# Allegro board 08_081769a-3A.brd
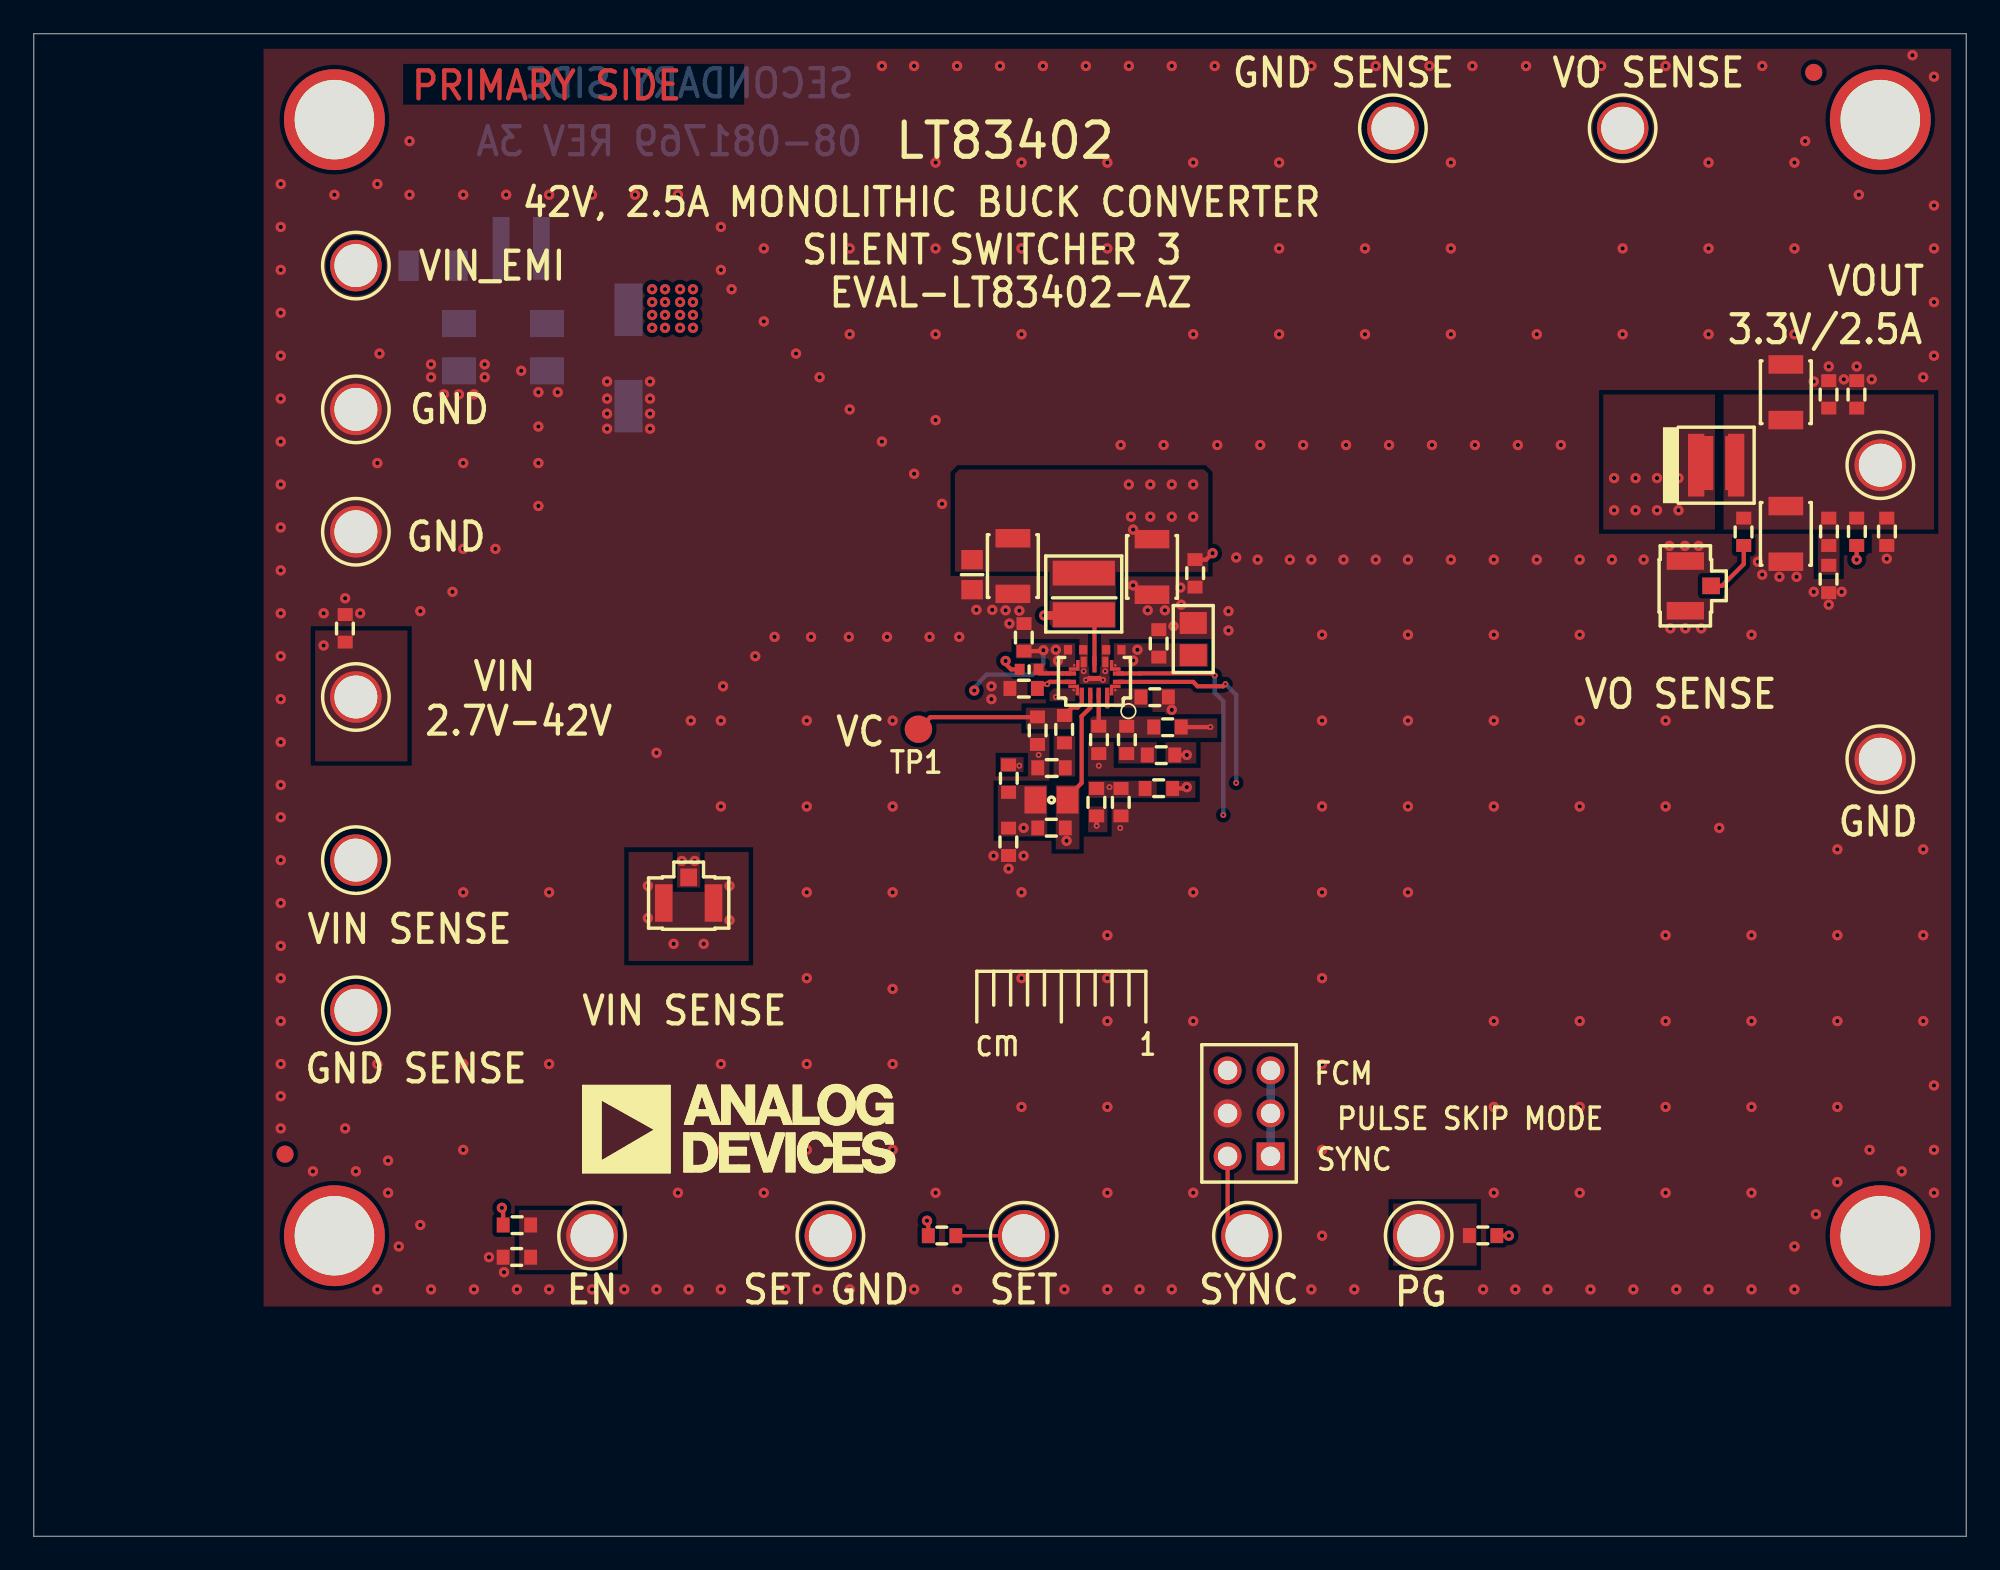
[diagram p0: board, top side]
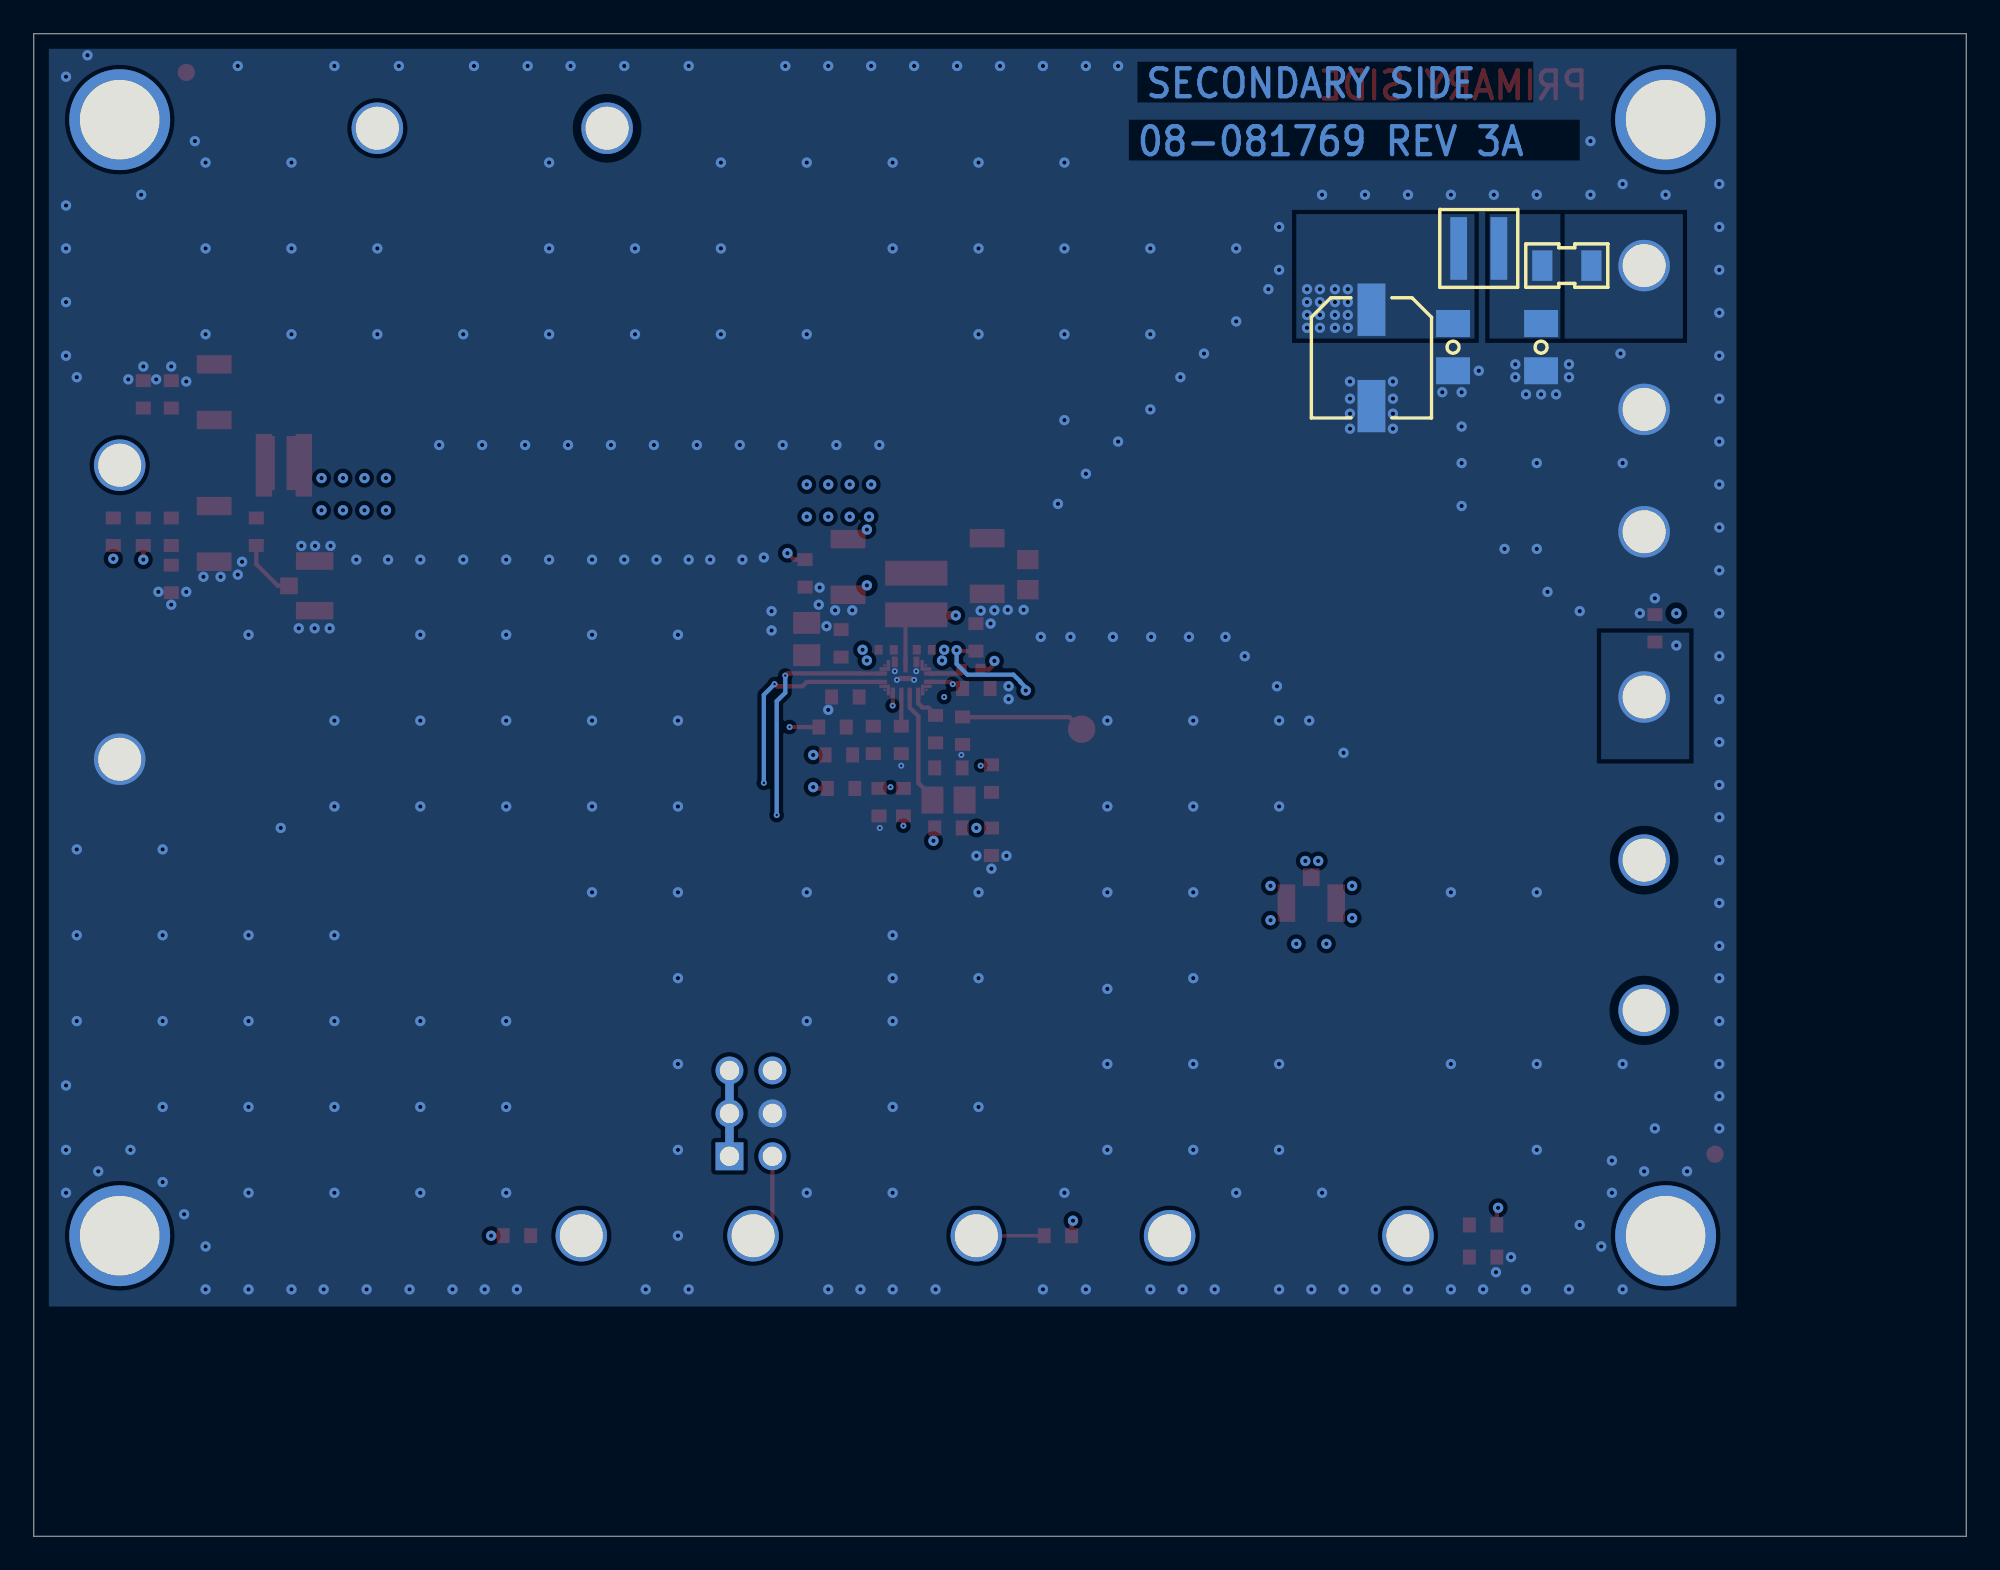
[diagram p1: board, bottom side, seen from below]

Outline 114.3 x 88.9 mm; copper layers: TOP, LAYER_2, LAYER_3, BOTTOM. Coordinates in mm from the lower left corner of the outline.
Outline path: 0,88.9 0,0 114.3,0 114.3,88.9 0,88.9

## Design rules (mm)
constraint set DEFAULT: min track width 0.203

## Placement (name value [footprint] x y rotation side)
C1  1uF  [C1206H71]  30.35 70.36 270 bottom
C2  2.2uF  [C0603]  18.41 53.72 90 top
C4  22uF  [CPLSMSQ260H315]  35.18 69.72 270 bottom
C5  4.7uF  [C0805H53]  68.58 53.09 90 top
C6  4.7uF  [C1206H71]  25.15 70.36 270 bottom
C7  1UF  [C0402#2]  63.88 52.45 180 top
C8  4700pF  [C0603]  60.2 45.47 180 top
C9  1UF  [C0402#2]  61.62 52.45 0 top
C10  2.2uF  [C0603]  68.68 56.97 270 top
C11  82PF  [C0603]  59.37 47.66 270 top
C12  1uF  [C0603]  58.55 50.17 180 top
C13  0.1uF  [C0402]  58.87 51.29 0 top
C14  1uF  [C0805H60]  60.2 43.56 180 top
C15  22uF  [C1210H106]  57.91 57.4 270 top
C16  22uF  [C1210H106]  66.14 57.35 270 top
C18  TBD0805  [C0805]  55.5 56.9 270 top
C19  22uF  [C1210H106]  103.63 67.69 90 top
C20  22uF  [C1210H106]  103.63 59.31 270 top
C21  2.2uF  [C0603]  109.6 59.44 270 top
C22  TBD0603  [C0603]  106.17 67.56 90 top
C23  TBD0603  [C0603]  107.82 67.56 90 top
C24  TBD0603  [C0603]  106.17 59.44 270 top
C25  1uF  [C0603]  58.57 53.19 90 top
C26  1uF  [C0603]  66.55 52.83 90 top
E1  2501-2-00-80-00-00-07-0  [CNMILLMAX2501]  19.05 75.18 90 top
E2  2501-2-00-80-00-00-07-0  [CNMILLMAX2501]  19.05 66.67 90 top
E3  2501-2-00-80-00-00-07-0  [CNMILLMAX2501]  19.05 40 90 top
E4  2501-2-00-80-00-00-07-0  [CNMILLMAX2501]  19.05 31.11 90 top
E5  2501-2-00-80-00-00-07-0  [CNMILLMAX2501]  71.75 17.78 0 top
E6  2501-2-00-80-00-00-07-0  [CNMILLMAX2501]  19.05 49.66 0 top
E7  2501-2-00-80-00-00-07-0  [CNMILLMAX2501]  19.05 59.44 0 top
E8  2501-2-00-80-00-00-07-0  [CNMILLMAX2501]  33.02 17.78 0 top
E9  2501-2-00-80-00-00-07-0  [CNMILLMAX2501]  81.92 17.78 0 top
E10  2501-2-00-80-00-00-07-0  [CNMILLMAX2501]  93.98 83.31 90 top
E11  2501-2-00-80-00-00-07-0  [CNMILLMAX2501]  80.39 83.31 270 top
E12  2501-2-00-80-00-00-07-0  [CNMILLMAX2501]  109.22 63.37 0 top
E13  2501-2-00-80-00-00-07-0  [CNMILLMAX2501]  109.22 45.97 0 top
E14  2501-2-00-80-00-00-07-0  [CNMILLMAX2501]  58.55 17.78 0 top
E15  2501-2-00-80-00-00-07-0  [CNMILLMAX2501]  47.12 17.78 0 top
FB1  800OHM AT 100MHZ  [L1206H71]  23.62 75.18 0 bottom
J5  RSP-122811-01  [CNSMASQ102H56]  38.73 37.47 180 top
J6  RSP-122811-01  [CNSMASQ102H56]  97.69 56.24 90 top
JP1  TSW-103-07-F-D  [CNSAMTEC2X3H330LD36]  73.15 22.48 90 top
L1  2.2UH  [LSMSQ157H83]  62.1 55.75 90 top
L2  4.7UH  [LSMSQ161H83]  28.83 76.2 0 bottom
L3  2.2UH  [LSMSQ157H122]  99.51 63.37 0 top
NOREF  -  []  343.12 241.69 0 top
NOREF#2  -  []  113.67 13.33 90 top
NOREF#3  -  []  113.67 88.27 180 top
NOREF#4  -  []  12.7 88.9 0 top
NOREF#5  -  [unnamed#2]  17.78 83.82 0 top
NOREF#6  -  [unnamed#2]  17.78 17.78 0 top
NOREF#7  -  []  12.7 12.7 90 top
NOREF#8  -  []  -102.74 -190.75 0 top
NOREF#9  -  []  275.21 77.85 0 top
NOREF#10  -  [unnamed#2]  109.22 17.78 0 top
NOREF#11  -  []  178.18 232.41 0 top
NOREF#12  -  [unnamed#2]  109.22 83.82 0 top
NOREF#13  -  []  61.77 101.24 0 top
NOREF#14  -  []  58.93 34.67 0 top
NOREF#15  -  [unnamed#2]  14.86 22.61 0 top
NOREF#16  -  [unnamed#2]  105.28 86.61 0 top
NOREF#17  -  []  13.33 13.33 0 top
NOREF#18  -  []  -60.71 -173.48 0 top
NOREF#19  -  []  13.33 88.27 270 top
NOREF#20  -  []  350.14 178.18 0 top
R1  1K  [R0603]  60.96 47.75 270 top
R2  TBD0603  [R0603]  53.72 17.78 180 top
R3  100K  [R0603]  28.57 18.41 0 top
R4  47.5K  [R0603]  66.29 49.66 0 top
R5  TBD0603  [R0603]  28.57 16.51 180 top
R6  33.2K  [R0603]  60.2 41.91 180 top
R7  0  [R0603]  64.64 47.12 90 top
R8  0.001  [R0612]  99.7 63.5 0 top
R9  TBD0603  [R0603]  67.06 47.88 0 top
R10  280K  [R0603]  66.55 44.25 180 top
R11  49.9K  [R0603]  64.31 43.43 270 top
R12  100K  [R0603]  85.73 17.79 180 top
R13  TBD0603  [R0603]  106.17 56.64 270 top
R14  0  [R0603]  66.67 46.23 0 top
R15  TBD0603  [R0603]  62.99 47.12 90 top
R16  TBD0603  [R0603]  107.82 59.44 90 top
R17  TBD0603  [R0603]  57.66 44.83 90 top
R18  0  [R0603]  57.66 41.09 270 top
R19  TBD0603  [R0603]  62.86 43.43 270 top
R22  0  [R0603]  101.14 59.44 270 top
TP1  NCTARGET_PAD_C62AU  [TPSMC62]  52.32 47.75 0 top
U1  LT83402  [QFN15_CP-15-1]  62.74 50.8 180 top

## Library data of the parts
C1 = CAP: Tolerance: 10; User Part Number: UPN; alternate symbols: (C1206H71); part number: CAP_SM-1UF,50V,10,E030213,C1206H71; tolerance: 10
C2 = CAP: Tolerance: 10; User Part Number: UPN; alternate symbols: (C0603); part number: CAP_SM-2.2UF,50V,10,E024995,C0603; tolerance: 10
C4 = CAPP: Tolerance: 20; User Part Number: UPN; alternate symbols: (CPLSMSQ260H315); part number: CAPP_SM-22UF,63V,20,E033596,CPLSMSQ260H315; tolerance: 20
C5 = CAP: Tolerance: 10; User Part Number: UPN; alternate symbols: (C0805H53); part number: CAP_SM-4.7UF,50V,10,E028468,C0805H53; tolerance: 10
C6 = CAP: Tolerance: 10; User Part Number: UPN; alternate symbols: (C1206H71); part number: CAP_SM-4.7UF,50V,10,E026699,C1206H71; tolerance: 10
C7 C9 = CAP: User Part Number: UPN; Tolerance: 10; alternate symbols: (C0402L); part number: CAP_SM-1UF,50V,10,E064438,C0402; tolerance: 10
C8 = CAP: Tolerance: 10; User Part Number: UPN; alternate symbols: (C0603); part number: CAP_SM-4700PF,50V,10,E000427,C0603; tolerance: 10
C10 C21 = CAP: Tolerance: 10; User Part Number: UPN; alternate symbols: (C0603); part number: CAP_SM-2.2UF,25V,10,E031885,C0603; tolerance: 10
C11 = CAP: Tolerance: 5; User Part Number: UPN; alternate symbols: (C0603); part number: CAP_SM-82PF,50V,5,E042666,C0603; tolerance: 5
C12 = CAP: Tolerance: 10; User Part Number: UPN; alternate symbols: (C0603); part number: CAP_SM-1UF,25V,10,E033832,C0603; tolerance: 10
C13 = CAP: Tolerance: 10; User Part Number: UPN; alternate symbols: (C0402); part number: CAP_SM-0.1UF,50V,10,E028943,C0402; tolerance: 10
C14 = CAP: Tolerance: 10; User Part Number: UPN; alternate symbols: (C0805H60); part number: CAP_SM-1UF,50V,10,E030886,C0805H60; tolerance: 10
C15 C16 C19 C20 = CAP: Tolerance: 10; User Part Number: UPN; alternate symbols: (C1210H106); part number: CAP_SM-22UF,25V,10,E025745,C1210H106; tolerance: 10
C18 = CAP: User Part Number: UPN; alternate symbols: (C0805); part number: CAP_SM-TBD0805,TBD0805,TBD0805,E000383,C0805
C22-C24 = CAP: User Part Number: UPN; alternate symbols: (C0603); part number: CAP_SM-TBD0603,TBD0603,TBD0603,E000382,C0603
C25 C26 = CAP: Tolerance: 10; User Part Number: UPN; alternate symbols: (C0603); part number: CAP_SM-1UF,50V,10,E023087,C0603; tolerance: 10
E1-E15 = CNTP1P: User Part Number: UPN; Tolerance: N/A; alternate symbols: (CNMILLMAX2501); part number: CNTP1P_TH-2501-2-00-80-00-00-07-0,E031108,CNMILLMAX2501; tolerance: N/A
FB1 = FERRITE: User Part Number: UPN; Tolerance: 25; alternate symbols: (L1206H71); part number: FERRITE_SM-800OHM AT 100MHZ,25,E067875,L1206H71; tolerance: 25
J5 J6 = CNBNC3P: User Part Number: UPN; Tolerance: N/A; alternate symbols: (CNSMASQ102H56); part number: CNBNC3P_SM-RSP-122811-01,E033920,CNSMASQ102H56; tolerance: N/A
JP1 = CN6P_ODD_EVEN: Tolerance: N/A; User Part Number: UPN; alternate symbols: (CNSAMTEC2X3H330LD36); part number: CN6P_ODD_EVEN_TH-TSW-103-07-F-D,E031502,CNSAMTEC2X3H330LD36; tolerance: N/A
L1 = IND: User Part Number: UPN; Tolerance: 20; alternate symbols: (LSMSQ157H83); part number: IND_SM-2.2UH,20,E051506,LSMSQ157H83; tolerance: 20
L2 = IND: User Part Number: UPN; Tolerance: 20; alternate symbols: (LSMSQ161H83); part number: IND_SM-4.7UH,20,E046383,LSMSQ161H83; tolerance: 20
L3 = IND: User Part Number: UPN; Tolerance: 20; alternate symbols: (LSMSQ157H122); part number: IND_SM-2.2UH,20,E054929,LSMSQ157H122; tolerance: 20
R1 = RES: Tolerance: 1; User Part Number: UPN; alternate symbols: (R0603); part number: RES_SM-1K,E003678,1/10W,1,R0603; tolerance: 1
R2 R5 R9 R13 R15-R17 R19 = RES: User Part Number: UPN; alternate symbols: (R0603); part number: RES_SM-TBD0603,E004050,TBD0603,TBD0603,R0603
R3 R12 = RES: Tolerance: 1; User Part Number: UPN; alternate symbols: (R0603); part number: RES_SM-100K,E010279,1/10W,1,R0603; tolerance: 1
R4 = RES: Tolerance: 1; User Part Number: UPN; alternate symbols: (R0603); part number: RES_SM-47.5K,E032237,1/10W,1,R0603; tolerance: 1
R6 = RES: Tolerance: 1; User Part Number: UPN; alternate symbols: (R0603); part number: RES_SM-33.2K,E028266,1/10W,1,R0603; tolerance: 1
R7 R14 R18 R22 = RES: Tolerance: JUMPER; User Part Number: UPN; alternate symbols: (R0603); part number: RES_SM-0,E007502,1/10W,JUMPER,R0603; tolerance: JUMPER
R8 = RES: User Part Number: UPN; Tolerance: 1; alternate symbols: (R0612); part number: RES_SM-0.001,E065605,1W,1,R0612; tolerance: 1
R10 = RES: Tolerance: 1; User Part Number: UPN; alternate symbols: (R0603); part number: RES_SM-280K,E020071,1/10W,1,R0603; tolerance: 1
R11 = RES: Tolerance: 1; User Part Number: UPN; alternate symbols: (R0603); part number: RES_SM-49.9K,E015342,1/10W,1,R0603; tolerance: 1
TP1 = NC1P: Tolerance: N/A; User Part Number: UPN; alternate symbols: (TPSMC62); part number: NC1P_SM-NCTARGET_PAD_C62AU,E050423,TPSMC62; tolerance: N/A
U1 = ADLT83402: User Part Number: UPN; Tolerance: N/A; alternate symbols: (QFN15_CP-15-1); part number: ADLT83402_SM-LT83402,E065562,QFN15_CP-15-1; tolerance: N/A

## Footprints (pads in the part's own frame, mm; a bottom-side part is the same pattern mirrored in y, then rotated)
C0402
  rect 0.584x0.66 smd: 1(-0.559,0) 2(0.559,0)
C0402#2
  rect 0.483x0.559 smd: 1(-0.45,0) 2(0.45,0)
C0603
  rect 0.762x0.889 smd: 1(-0.813,0) 2(0.813,0)
C0805
  rect 1.143x1.27 smd: 1(-0.889,0) 2(0.889,0)
C0805H53
  rect 1.295x1.6 smd: 1(-0.953,0) 2(0.953,0)
C0805H60
  rect 1.295x1.6 smd: 1(-0.953,0) 2(0.953,0)
C1206H71
  rect 1.6x2.007 smd: 1(-1.397,0) 2(1.397,0)
C1210H106
  rect 1.092x2.057 smd: 1(-1.646,0) 2(1.646,0)
CNMILLMAX2501
  round 3.048 hole 2.54: 1(0,0)
CNSAMTEC2X3H330LD36
  rect 1.651x1.651 hole 1.143: 1(0,0)
  round 1.651 hole 1.143: 2(0,2.54) 3(2.54,0) 4(2.54,2.54) 5(5.08,0) 6(5.08,2.54)
CNSMASQ102H56
  rect 0.991x1.041 smd: 1(0,-1.521)
  rect 1.041x2.21 smd: 2(-1.471,0) 3(1.471,0)
CPLSMSQ260H315
  rect 3.099x1.651 smd: N(2.85,0) P(-2.85,0)
L1206H71
  rect 1.194x1.803 smd: 1(-1.45,0) 2(1.45,0)
LSMSQ157H83
  rect 1.473x3.683 smd: 1(-1.232,0) 2(1.232,0)
LSMSQ157H122
  rect 0.965x3.708 smd: 1(-1.181,0) 2(1.181,0)
LSMSQ161H83
  rect 0.991x3.708 smd: 1(-1.19,0) 2(1.19,0)
QFN15_CP-15-1
  custom 0.159x0.159 smd: 1(-1.229,0.729) 4(-1.229,-0.729) 8(1.2,-0.729) 11(1.229,0.729)
  rect 0.66x0.254 smd: 2(-1.42,0.25) 3(-1.42,-0.25) 9(1.42,-0.25) 10(1.42,0.25)
  rect 0.356x0.635 smd: 5(-0.64,-0.932) 7(0.64,-0.932)
  rect 0.254x0.94 smd: 6(0,-0.78)
  rect 0.254x0.66 smd: 12(0.75,0.92) 13(0.25,0.92) 14(-0.25,0.92) 15(-0.75,0.92)
  rect 0.813x0.305 smd: 16(0,0.051)
R0603
  rect 0.762x0.889 smd: 1(-0.813,0) 2(0.813,0)
R0612
  rect 0.94x3.2 smd: 1(-0.82,0) 2(0.82,0)
TPSMC62
  round 1.626 smd: 1(0,0)
unnamed#2
  round 5.969 hole 4.699 unplated: (0,0)

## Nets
GND_POWER: C1.2(N2) C2.2(N2) C4.N(N2) C5.2(N2) C6.2(N2) C7.2(N2) C8.2(N2) C9.2(N2) C10.2(N2) C11.2(N2) C12.2(N2) C15.2(N2) C16.2(N2) C18.2(N2) C19.2(N2) C20.2(N2) C21.2(N2) C22.2(N2) C23.2(N2) C25.2(N2) C26.2(N2) E2.1(N1) E4.1(N1) E7.1(N1) E11.1(N1) E13.1(N1) J5.2 J5.3(SH2) J6.2 J6.3(SH2) JP1.4 R4.2(N2) R5.2(N2) R11.2(N2) R13.2(N2) R15.1 R17.2(N2) R18.2(N2) U1.5 U1.7 U1.16
VIN: C1.1 C2.1 C4.P C5.1 C7.1 C9.1 C25.1 C26.1 E3.1(N1) E6.1(N1) J5.1 L2.2(N2) R3.1 U1.4 U1.8(VIN_2)
BST: C13.2(N2) U1.9
INTVCC: C12.1 JP1.6(N6) R19.2(N2) U1.10
OUTS: R7.2(N2) R9.1 R15.2(N2) U1.14
PG: E9.1(N1) R12.2(N2) U1.2
PGFB: R10.2(N2) R11.1 R19.1 U1.15
SET: C14.1 R2.2(N2) R6.1 U1.13
SW: C13.1 L1.1 U1.6
SYNC: JP1.1 JP1.3 JP1.5 U1.3
UNNAMED_2_ADLT83402_I194_EN: E8.1(N1) R3.2(N2) R5.1 U1.11
UNNAMED_2_ADLT83402_I194_RT: R4.1 U1.1
UNNAMED_2_CAP_I105_N2: C24.2(N2) R13.1
UNNAMED_2_CAP_I141_N1: C10.1 C15.1 C16.1 C18.1 E10.1(N1) L1.2(N2) L3.1 R8.1 R10.1 R14.2(N2)
UNNAMED_2_CAP_I218_N1: C6.1 FB1.2(N2) L2.1
UNNAMED_2_CAP_I232_N2: C14.2(N2) E15.1(N1) R6.2(N2) R17.1 R18.1
UNNAMED_2_CAP_I244_N1: C8.1 R1.2(N2)
UNNAMED_2_CN6PODDEVEN_I122_N2: E5.1(N1) JP1.2
UNNAMED_2_CNBNC3P_I240_CNTR: J6.1 R22.2(N2)
UNNAMED_2_CNTP1P_I204_N1: E1.1(N1) FB1.1
UNNAMED_2_CNTP1P_I231_N1: E14.1(N1) R2.1
UNNAMED_2_RES_I157_N1: R7.1 R14.1
UNNAMED_2_RES_I219_N2: R9.2(N2) R16.1
VC: C11.1 R1.1 TP1.1(N1) U1.12
VOUT: C19.1 C20.1 C21.1 C22.1 C23.1 C24.1 E12.1(N1) L3.2(N2) R8.2(N2) R12.1 R16.2(N2) R22.1

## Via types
v1: diameter 0.61, hole 0.254, TOP to BOTTOM, 389 vias
v2: diameter 0.356, hole 0.152, TOP to BOTTOM, 18 vias

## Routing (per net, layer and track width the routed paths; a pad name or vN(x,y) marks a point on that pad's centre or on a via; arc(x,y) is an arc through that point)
GND_POWER: length 205.3
  TOP w0.254: 22.8,54.67 v1(22.86,54.74)
  LAYER_3 w0.254: v1(109.6,57.84) 109.09,57.33 109.09,55.12 100.2,46.23 70.36,46.23 69.72,45.59 69.72,44.07 68.83,43.18 62.48,43.18 60.07,45.59 v2(58.29,45.59) ; E4.1 47.12,31.11 52.83,36.83 52.83,48.51 55.12,50.8 56.39,50.8 56.64,50.55 v1(56.64,50.29) ; v1(65.02,56.26) 65.02,57.91 62.36,60.58 62.36,69.22 67.12,73.98 75.37,73.98 75.44,73.91 85.6,73.91 87.76,76.07 87.76,82.42 86.87,83.31 E11.1 ; 37.47,40.26 37.47,42.16 36.07,43.56 17.02,43.56 15.49,45.08 15.49,52.96 v1(17.14,54.61)
  vias: v1(14.6,80.01) v1(14.6,77.47) v1(14.6,74.93) v1(14.6,72.39) v1(14.6,69.85) v1(14.6,67.31) v1(14.6,64.77) v1(14.6,62.23) v1(14.6,59.69) v1(14.6,57.15) v1(14.6,54.61) v1(14.6,52.07) v1(14.6,49.53) v1(14.6,46.99) v1(14.6,44.45) v1(14.6,42.55) v1(14.6,40) v1(14.6,37.47) v1(14.6,34.92) v1(14.6,33.02) v1(14.6,30.48) v1(14.6,27.94) v1(14.6,26.04) v1(14.6,24.13) v1(16.51,21.59) v1(17.78,79.38) v1(18.41,55.5) v1(18.41,24.13) v1(19.05,21.59) v1(19.3,54.61) v1(20.32,80.01) v1(20.32,63.5) v1(20.32,27.94) v1(20.32,14.6) v1(20.45,69.98) v1(20.95,22.23) v1(20.95,20.32) v1(21.59,17.14) v1(22.23,82.55) v1(22.23,79.38) v1(22.86,18.41) v1(23.49,69.34) v1(23.49,68.58) v1(23.49,14.6) v1(24.26,67.56) v1(24.77,55.88) v1(25.15,67.56) v1(25.4,79.38) v1(25.4,63.5) v1(25.4,58.42) v1(25.4,38.1) v1(25.4,27.94) v1(25.4,22.86) v1(26.04,67.56) v1(26.04,14.6) v1(26.67,69.34) v1(26.67,68.58) v1(26.92,16.51) v1(27.3,58.42) v1(27.81,15.62) v1(27.94,79.38) v1(28.57,14.6) v1(28.83,68.96) v1(29.84,67.69) v1(29.84,65.66) v1(29.84,63.5) v1(29.84,60.96) v1(30.48,79.38) v1(30.48,38.1) v1(30.48,27.94) v1(30.48,14.6) v1(30.99,67.69) v1(33.02,79.38) v1(33.02,14.6) v1(33.91,68.33) v1(33.91,67.31) v1(33.91,66.42) v1(33.91,65.53) v1(34.92,14.6) v1(35.56,79.38) v1(36.32,38.48) v1(36.32,36.58) v1(36.45,68.33) v1(36.45,67.31) v1(36.45,66.42) v1(36.45,65.53) v1(36.83,46.36) v1(36.83,14.6) v1(37.85,35.05) v1(38.1,79.38) v1(38.1,20.32) v1(38.73,14.6) v1(38.86,48.26) v1(39.62,35.05) v1(40.64,77.47) v1(40.64,74.93) v1(40.64,48.26) v1(40.64,43.18) v1(40.64,27.94) v1(40.64,22.86) v1(40.64,14.6) v1(40.77,50.29) v1(41.15,38.48) v1(41.15,36.45) v1(41.27,73.79) v1(42.67,52.07) v1(43.18,76.2) v1(43.18,71.88) v1(43.18,20.32) v1(43.81,53.21) v1(44.45,14.6) v1(45.08,69.98) v1(45.72,48.26) v1(45.72,43.18) v1(45.72,38.1) v1(45.72,33.02) v1(45.72,27.94) v1(45.72,22.86) v1(45.97,53.21) v1(46.36,14.6) v1(46.48,68.58) v1(48.21,53.21) v1(48.26,76.2) v1(48.26,71.12) v1(48.26,66.67) v1(48.26,14.6) v1(50.17,87) v1(50.17,64.77) v1(50.47,53.21) v1(50.8,48.26) v1(50.8,43.18) v1(50.8,38.1) v1(50.8,32.38) v1(50.8,27.94) v1(50.8,22.86) v1(52.07,87) v1(52.07,62.86) v1(52.07,14.6) v1(52.98,53.21) v1(53.34,81.28) v1(53.34,76.2) v1(53.34,71.12) v1(53.34,66.04) v1(53.34,20.32) v1(53.72,61.09) v1(54.61,87) v1(54.61,14.6) v1(54.74,53.21) v1(55.75,54.81) v1(56.64,49.53) v1(56.69,54.81) v1(56.77,40.26) v1(57.15,87) v1(57.48,54.79) v1(57.71,54) v1(57.66,39.5) v1(58.29,54.76) v1(58.42,81.28) v1(58.42,76.2) v1(58.42,71.12) v1(58.42,38.1) v1(58.42,33.02) v1(58.42,25.4) v1(58.55,40.26) v1(59.69,87) v1(60.96,14.6) v1(62.23,87) v1(63.5,81.28) v1(63.5,76.2) v1(63.5,35.56) v1(63.5,33.02) v1(63.5,30.48) v1(63.5,25.4) v1(63.5,20.32) v1(63.5,14.6) v1(64.29,64.57) v1(64.77,87) v1(65.41,14.6) v1(65.89,54.79) v1(66.83,64.57) v1(66.9,54.79) v1(67.31,87) v1(67.31,48.89) v1(67.31,14.6) v1(67.41,53.85) v1(67.82,56.13) v1(67.87,55.12) v1(68.58,81.28) v1(68.58,71.12) v1(68.58,38.1) v1(68.58,30.48) v1(68.58,20.32) v1(69.85,87) v1(70,64.57) v1(70.66,54.74) v1(70.66,53.59) v1(71.12,57.91) v1(72.39,57.78) v1(72.54,64.57) v1(73.66,81.28) v1(73.66,76.2) v1(73.66,71.12) v1(74.3,57.78) v1(75.08,64.57) v1(75.56,87) v1(75.56,57.78) v1(75.56,14.6) v1(76.2,53.34) v1(76.2,48.26) v1(76.2,43.18) v1(76.2,38.1) v1(76.2,33.02) v1(76.2,27.94) v1(76.2,22.86) v1(76.2,17.78) v1(77.47,57.78) v1(77.62,64.57) v1(78.11,14.6) v1(78.74,76.2) v1(78.74,71.12) v1(79.38,87) v1(79.38,57.78) v1(80.16,64.57) v1(81.28,57.78) v1(81.28,53.34) v1(81.28,48.26) v1(81.28,43.18) v1(81.28,38.1) v1(82.55,87) v1(82.7,64.57) v1(83.82,81.28) v1(83.82,76.2) v1(83.82,71.12) v1(83.82,57.78) v1(85.09,87) v1(85.24,64.57) v1(85.73,14.6) v1(86.36,57.78) v1(86.36,53.34) v1(86.36,48.26) v1(86.36,43.18) v1(86.36,30.48) v1(86.36,25.4) v1(86.36,20.32) v1(87.63,14.6) v1(87.78,64.57) v1(88.27,87) v1(88.9,71.12) v1(88.9,57.78) v1(89.53,14.6) v1(90.32,64.57) v1(91.44,57.78) v1(91.44,53.34) v1(91.44,48.26) v1(91.44,43.18) v1(91.44,30.48) v1(91.44,25.4) v1(91.44,20.32) v1(92.08,14.6) v1(92.71,87) v1(93.34,57.78) v1(93.98,76.2) v1(93.98,71.12) v1(94.62,14.6) v1(95.22,57.78) v1(96.52,87) v1(96.52,48.26) v1(96.52,43.18) v1(96.52,35.56) v1(96.52,30.48) v1(96.52,25.4) v1(96.52,20.32) v1(96.75,58.6) v1(96.8,53.72) v1(97.16,14.6) v1(97.66,58.6) v1(97.69,53.72) v1(98.48,58.6) v1(98.63,53.72) v1(99.06,81.28) v1(99.06,76.2) v1(99.06,71.12) v1(99.06,14.6) v1(99.7,41.91) v1(101.6,53.34) v1(101.6,35.56) v1(101.6,30.48) v1(101.6,25.4) v1(101.6,20.32) v1(101.6,14.6) v1(101.98,57.66) v1(102.23,87) v1(102.23,56.9) v1(103.25,56.77) v1(104.14,81.28) v1(104.14,76.2) v1(104.14,71.12) v1(104.14,17.14) v1(104.14,14.6) v1(104.27,56.77) v1(104.78,82.55) v1(105.28,68.33) v1(105.28,55.88) v1(105.41,19.05) v1(106.17,69.22) v1(106.17,55.12) v1(106.68,40.64) v1(106.68,35.56) v1(106.68,30.48) v1(106.68,25.4) v1(106.68,20.95) v1(106.93,55.88) v1(107.06,68.45) v1(107.82,69.22) v1(107.95,79.38) v1(108.59,22.86) v1(108.71,68.45) v1(110.49,21.59) v1(111.12,87.63) v1(111.76,68.58) v1(111.76,40.64) v1(111.76,35.56) v1(111.76,30.48) v1(112.39,86.36) v1(112.39,78.74) v1(112.39,76.2) v1(112.39,73.03) v1(112.39,69.85) v1(112.39,26.67) v1(112.39,22.86) v1(112.39,20.32) v2(59.44,46.23) v2(62.1,51.18) v2(62.23,50.67) v2(62.99,45.59) v2(63.25,50.67) v2(63.37,51.18) v2(64.26,41.91)
VIN: length 153.8
  TOP w0.254: R3.1 27.76,19.35 v1(27.69,19.43) ; v1(59.72,52.43) 59.66,52.37 C25.1
  LAYER_3 w0.254: v1(17.14,52.7) 16,51.56 16,45.47 17.27,44.2 36.45,44.2 38.1,42.55 38.1,40.18 v1(38.33,39.95) ; E3.1 19.05,35.94 23.37,31.62 46.86,31.62 52.32,37.08 52.32,48.77 54.89,51.33 56.67,51.33 56.95,51.05 59.82,51.05 v1(60.58,51.82) 60.58,51.69 ; v1(55.63,50.04) 54.1,48.51 54.1,33.78 49.28,28.96 37.21,28.96 v1(27.69,19.43)
  BOTTOM w0.254: v1(55.63,50.04) 55.63,50.22 55.96,50.55 55.96,50.58 56.36,50.98 59.08,50.98 59.72,51.61 v1(59.72,52.43)
  vias: v1(36.58,73.79) v1(36.58,73.03) v1(36.58,72.26) v1(36.58,71.5) v1(37.34,73.79) v1(37.34,73.03) v1(37.34,72.26) v1(37.34,71.5) v1(38.23,73.79) v1(38.23,73.03) v1(38.23,72.26) v1(38.23,71.5) v1(38.99,73.79) v1(38.99,73.03) v1(38.99,72.26) v1(38.99,71.5) v1(39.09,39.95) v1(60.45,52.45) v1(65.02,51.82) v1(65.28,52.45)
BST: length 1.9
  TOP w0.254: U1.9 60.86,51.05 60.86,51.05 59.46,51.05
INTVCC: length 35.8
  TOP w0.254: R19.2 v2(62.86,42.04) ; U1.10 60.08,50.55 v2(59.94,50.42) 59.61,50.42 C12.1
  LAYER_3 w0.254: JP1.6 70.61,34.29 v2(62.86,42.04) 62.1,42.04 59.44,44.7 58.17,44.7 57.53,45.34 57.53,47.75 58.55,48.77 60.58,48.77 61.09,49.28 61.09,50.17 60.83,50.42 v2(59.94,50.42)
OUTS: length 1.9
  TOP w0.254: 62.99,48.01 U1.14
PG: length 43.9
  TOP w0.25: U1.2 68.58,50.55 68.83,50.29
  TOP w0.254: v2(70.48,50.42) 70.36,50.29 68.83,50.29
  LAYER_3 w0.254: v2(71.12,44.58) 81.92,33.78 E9.1
  BOTTOM w0.254: v2(70.48,50.42) 71.12,49.78 v2(71.12,44.58)
PGFB: length 5.6
  TOP w0.254: U1.15 63.49,49.16 v2(63.5,49.15)
  LAYER_3 w0.254: v2(63.63,44.32) 63.63,49.02 v2(63.5,49.15)
SET: length 33.9
  TOP w0.254: U1.13 62.49,49.03 61.98,48.51 61.98,44.57 61.1,43.69 ; R2.2 52.91,18.59 v1(52.83,18.67)
  LAYER_3 w0.254: v1(52.83,18.67) 52.45,19.05 52.45,22.86 61.09,31.5 v1(61.09,41.15)
SW: length 9.6
  TOP w0.254: C13.1 57.8,51.29 57.48,51.61 v1(57.48,51.79) ; 62.74,53.89 U1.6
  TOP w0.508: 62.06,54.48 v1(59.77,54.48)
  LAYER_3 w0.254: v1(57.48,51.79) 57.84,51.79 59.77,53.72 v1(59.77,54.48)
SYNC: length 35.6
  TOP w0.25: v2(69.85,50.93) 69.73,51.05 69.68,51.05 69.67,51.05 65.45,51.05 65.45,51.05 U1.3
  LAYER_3 w0.254: JP1.5 73.15,39.88 v2(70.36,42.67)
  BOTTOM w0.254: v2(69.85,50.93) 69.85,49.91 70.36,49.4 v2(70.36,42.67)
  BOTTOM w0.508: JP1.5 JP1.1
UNNAMED_2_ADLT83402_I194_EN: length 51.4
  LAYER_3 w0.254: E8.1 33.02,19.68 39.37,26.04 50.67,26.04 55.37,30.73 55.37,47.12 57.94,49.68 v2(60.45,49.66)
UNNAMED_2_CAP_I141_N1: length 83.5
  TOP w0.254: v1(68.2,44.32) 68.12,44.25 R10.1 ; R14.2 v1(68.2,46.23) ; C10.1 69.34,57.78 v1(69.72,58.17)
  LAYER_3 w0.254: v1(68.2,46.23) 68.2,51.31 69.09,52.2 69.09,56.64 68.58,57.15 v1(68.58,60.33) ; E10.1 89.41,83.31 88.27,82.17 88.27,75.82 85.85,73.41 67.31,73.41 62.86,68.96 62.86,60.83 64.14,59.56 v1(65.02,59.56) ; v1(68.2,44.32) 68.96,45.08 68.96,51.05 69.72,51.82 v1(69.72,58.17)
  vias: v1(64.77,62.23) v1(64.9,60.33) v1(66.04,62.23) v1(66.04,60.33) v1(67.31,62.23) v1(67.31,60.33) v1(68.58,62.23) v1(93.47,62.61) v1(93.47,60.71) v1(94.74,62.61) v1(94.74,60.71) v1(96.01,62.61) v1(96.01,60.71) v1(97.28,62.61) v1(97.28,60.71)
UNNAMED_2_CAP_I232_N2: length 32.6
  LAYER_3 w0.254: E15.1 50.42,17.78 51.94,19.3 51.94,23.24 60.45,31.75 60.45,40.39 58.93,41.91 v1(58.55,41.91)
UNNAMED_2_CN6PODDEVEN_I122_N2: length 5.4
  TOP w0.254: JP1.2 70.61,18.54 71.37,17.78 E5.1
UNNAMED_2_CNBNC3P_I240_CNTR: length 3.6
  TOP w0.254: R22.2 101.14,57.52 99.86,56.24 J6.1
UNNAMED_2_CNTP1P_I231_N1: length 4
  TOP w0.203: E14.1 R2.1
UNNAMED_2_RES_I219_N2: length 48.6
  TOP w0.254: v1(107.82,57.78) R16.1 ; R9.2 v2(69.6,47.88)
  LAYER_3 w0.254: v2(69.6,47.88) 69.6,47.5 70.36,46.74 99.95,46.74 108.59,55.37 108.59,57.15 107.95,57.78 v1(107.82,57.78)
VC: length 9.2
  TOP w0.254: TP1.1 53.03,48.46 59.37,48.46 ; U1.12 61.99,49.29 61.73,49.03 61.39,49.03 60.96,48.6
VOUT: length 67
  TOP w0.254: v1(87.25,17.78) 87.24,17.79 R12.1
  LAYER_3 w0.254: E12.1 109.73,63.37 112.78,60.33 112.78,29.08 101.47,17.78 v1(87.25,17.78)

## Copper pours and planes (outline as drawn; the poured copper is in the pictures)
GND_POWER on TOP: 35.18,40.49 35.18,34.04 42.29,34.04 42.29,40.49
GND_POWER on TOP: 13.59,88.01 113.41,88.01 113.41,13.59 13.59,13.59 ; 7 cut-outs
GND_POWER on TOP: 57.15,46.1 57.15,45.21 58.55,45.21 58.55,46.1
GND_POWER on BOTTOM: 13.59,88.01 113.41,88.01 113.41,13.59 13.59,13.59 ; 13 cut-outs
GND_POWER on LAYER_2: 13.59,88.01 113.28,88.01 113.28,13.59 13.59,13.59 ; 13 cut-outs
GND_POWER on LAYER_3: 34.92,40.51 34.92,33.53 42.55,33.53 42.55,40.51
GND_POWER on LAYER_3: 13.59,88.01 113.41,88.01 113.41,13.59 13.59,13.59 ; 10 cut-outs
VIN on TOP: 58.09,52.83 61.59,52.83 61.59,51.44 60.1,51.44 60.1,51.79 59.94,51.94 58.09,51.94
VIN on TOP: 38.05,40.49 38.05,38.38 39.42,38.38 39.42,40.49
VIN on TOP: 63.88,51.44 69.47,51.44 69.47,52.83 63.88,52.83
VIN on TOP: 16.64,53.59 16.64,45.85 22.1,45.85 22.1,53.59
VIN on BOTTOM: 29.08,78.23 29.08,70.87 39.62,70.87 39.62,78.23
VIN on BOTTOM: 16.38,53.47 16.38,45.97 21.59,45.97 21.59,53.47
VIN on LAYER_3: 31.88,74.3 39.24,74.3 53.21,60.33 61.98,60.33 64.52,57.78 64.52,54.61 65.79,53.34 65.79,51.69 65.56,51.46 64.24,51.46 63.63,52.07 61.85,52.07 61.21,51.44 59.59,51.44 59.33,51.69 59.33,54.66 58.62,55.37 55.5,55.37 54.53,54.41 42.72,54.41 34.16,45.85 18.54,45.85 17.14,47.24 17.14,51.82 19.05,53.72 24.64,53.72 31.88,60.96
VIN on LAYER_3: 37.85,40.51 37.85,38.35 39.5,38.35 39.5,40.51
INTVCC on TOP: 62.36,43.18 62.36,41.66 63.5,41.66 63.5,43.18
OUTS on TOP: 62.48,48.39 62.48,47.24 66.67,47.24 66.67,48.51 62.61,48.51
PG on TOP: 80.39,19.68 80.39,16 85.34,16 85.34,19.68
PGFB on TOP: 62.36,44.7 62.36,43.69 66.42,43.69 66.42,44.7
SET on TOP: 60.45,44.45 60.45,40.64 61.85,40.64 61.85,44.45
SW on TOP: 60.07,55.37 60.07,53.97 60.33,53.72 64.01,53.72 64.01,55.37
UNNAMED_2_ADLT83402_I194_EN on TOP: 60.07,49.91 60.07,49.4 61.59,49.4 61.59,50.17 60.33,50.17
UNNAMED_2_ADLT83402_I194_EN on TOP: 28.7,19.3 28.7,15.75 34.54,15.75 34.54,19.3
UNNAMED_2_ADLT83402_I194_RT on TOP: 63.88,50.17 65.91,50.17 65.91,49.02 63.88,49.02
UNNAMED_2_CAP_I105_N2 on TOP: 105.54,59.31 105.54,56.9 106.81,56.9 106.81,59.31
UNNAMED_2_CAP_I141_N1 on TOP: 54.48,62.86 54.48,57.07 60.07,57.07 60.07,55.63 64.01,55.63 64.01,57.05 69.47,57.05 69.47,62.86 69.22,63.12 54.74,63.12
UNNAMED_2_CAP_I141_N1 on TOP: 66.93,44.7 66.93,43.69 68.71,43.69 68.71,44.7
UNNAMED_2_CAP_I141_N1 on TOP: 66.93,46.99 66.93,45.72 68.76,45.72 68.76,46.99
UNNAMED_2_CAP_I141_N1 on TOP: 92.84,67.56 92.84,59.56 99.44,59.56 99.44,67.56
UNNAMED_2_CAP_I141_N1 on LAYER_3: 64.26,63.5 64.26,59.18 98.42,59.18 98.42,63.5
UNNAMED_2_CAP_I218_N1 on BOTTOM: 24,78.23 24,70.87 28.19,70.87 28.19,78.23
UNNAMED_2_CAP_I232_N2 on TOP: 57.02,44.45 59.94,44.45 59.94,41.4 57.02,41.4
UNNAMED_2_CAP_I244_N1 on TOP: 60.33,47.37 60.33,44.96 61.59,44.96 61.59,47.37
UNNAMED_2_CNTP1P_I204_N1 on BOTTOM: 16.76,78.23 16.76,70.87 23.75,70.87 23.75,78.23
UNNAMED_2_RES_I157_N1 on TOP: 64.14,46.99 64.14,45.72 66.42,45.72 66.42,46.99
UNNAMED_2_RES_I219_N2 on TOP: 67.44,48.39 67.44,47.24 70,47.24 70,48.39
VC on TOP: 58.67,49.02 58.67,47.75 61.47,47.75 61.47,49.02
VOUT on TOP: 99.95,59.56 112.39,59.56 112.39,67.56 99.95,67.56

Small or netless copper shapes (teardrops, artwork), in the pictures only: 1 on TOP

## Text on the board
BOTTOM: SECONDARY SIDE | 08-081769 REV 3A
User.Comments: XXX | C | FOR JP1: INSTALL SHUNT ACROSS PIN5 AND PIN6. | 5.    INSTALL INDUCTORS L1 AS SHOWN BELOW. | FOOTPRINT | PIN1 INDICATOR | PCB : SECONDARY | PCB : PRIMARY | PART | TURRETS
TOP: PRIMARY SIDE
Ref Des/Silkscreen Top: FCM | SYNC | PULSE SKIP MODE | 42V, 2.5A MONOLITHIC BUCK CONVERTER | SILENT SWITCHER 3 | EVAL-LT83402-AZ | VIN SENSE | GND SENSE | GND | VIN_EMI | VIN | 2.7V-42V | EN | SET GND | VC | SET | PG | VO SENSE | 3.3V/2.5A | VOUT | LT83402
PAGE_OUTLINE: INIATIAL RELEASE | EVAL-LT83402-AZ | -081769 | 3A
BODY_CENTER: FAB NOTES REVISION: 2ND NOVEMBER 2022 | 8.   IMPEDANCE REQUIREMENTS: IF NO STACKUP IS DEFINED, THE VENDOR IS ALLOWED TO ADJUST THE DIELECTRIC | 13.  PLATING SPECIFICATION: | 9.   FILLET OPTIONS TO ENHANCE RELIABILITY AT PAD JUNCTIONS WHERE SPACING PERMITS. | 10.  THIEVING: | 11.  LAYER TO LAYER REGISTRATION SHALL BE WITHIN 0.003 INCHES. | 12.  DRILL SIZES ARE FINISHED HOLE SIZES. ALL HOLES SHALL BE LOCATED WITHIN 0.005 INCHES DTP,UNLESS SPECIFIED. | 14.  SURFACE FINISH: | 15.  SOLDERMASK: | 1.   DIMENSIONS ARE IN INCHES (EXCEPT WHERE NOTED). | ALL DOCUMENTS & SPECIFICATIONS REFERRED TO BELOW SHOULD BE THE LATEST REVISIONS. | 2.  BOARD MATERIAL:(USE CHECKED ITEMS) | 3.   ALL LAMINATES & BONDING MATERIALS SHOULD BE SELECTED FROM IPC-4101 OR IPC-4103,(TG>170 DEGC TD>300 DEGC) | 4.   REFER TO IPC-6010 SERIES, CLASS 2 FOR FABRICATION. | 5.   REFER TO LAMINATION DIAGRAM FOR OVERALL BOARD THICKNESS, TOLERANCE APPLIES AFTER ALL LAMINATION AND PLATING | 6.   BOW & TWIST NOT TO EXCEED 0.0075 INCHES (0.75%) PER LINEAR INCH AND SHOULD BE MEASURED PER IPC-TM-650, METHOD 2.4.22. | 7.   ACCEPTABILITY PER ADI SPECIFICATION TST00115. | 16.  APPLY SILKSCREEN TO BOTH SIDES USING A NON-CONDUCTIVE, EPOXY BASED INK PER ARTWORK. | ( ) FILLETS ALLOWED | (X) FILLETS NOT ALLOWED | ( ) VENDOR MAY ADD THIEVING TO COMPENSATE FOR LOW COPPER DENSITY AREAS MAINTAINING A MINIMUM | (X) VENDOR MAY NOT ADD THIEVING TO COMPENSATE FOR LOW COPPER DENSITY AREAS. | (X) LPI | ( ) OTHER_________ | COLOR | (X) GREEN | (X) WHITE | ( ) OTHER | HINDER PROPER SOLDER WICKING. BARREL RELIEF ON SOLDERMASK ALLOWED IN UNFILLED VIA IN PAD HOLES. | (X) REFER TO LAMINATION DIAGRAM FOR FINISHED COPPER WEIGHT/THICKNESS REQUIRMENTS | (X) IMMERSION GOLD (ENIG) 1.58-3.94 MICRO INCHES OVER 118-236 MICRO INCHES MIN. OF ELECTROLESS NICKEL PER IPC-4552 | ( ) OSP (ORGANIC SOLDERABILITY PRESERVATIVE) | ( ) IMMERSION SILVER | ( ) SOFT WIRE BONDABLE GOLD 30-50 MICRO INCHES OF SOFT WIRE | ( ) EDGE CONNECTOR FINGERS ARE TO BE PLATED WITH 100 MICRO-INCHES(.0001") OF LOW STRESS | THICKNESS & TRACE WIDTHS TO MEET THE IMPEDANCE REQUIREMENT. IF SPECIFIED, THE VENDOR MUST | TRACE WIDTH & SPACING THAT IMPACT THE REQUIREMENTS MUST HAVE WRITTEN APPROVAL FROM ADI. | MINIMUM BARREL PLATING OF 0.001 INCHES. PLATED HOLES SHALL NOT BE ROUGH OR IRREGULAR SO AS TO | SOLDERMASK OVER BARE COPPER OR BARE GOLD (BOTH SIDES) TO MEET IPC-SM-840. | IF PRESENT,DO NOT MODIFY SOLDERMASK DEFINED PADS (MASK OPENINGS LESS THAN COPPER PAD) WITHOUT APPROVAL. | MEET THE REQUIREMENTS LISTED IN THE IMPEDANCE TABLE. ANY ADJUSTMENT MADE TO THE DEFINED STACKUP, | PROCESSES. FINISHED THICKNESS MEASURED FROM TOP COPPER TO BOTTOM COPPER. | (X)  ISOLA 370HR OR S1000-2 OR IT180 OR EQUIVALENT | ( )  ISOLA-FR408HR OR EQUIVALENT | ( )  ISOLA IS410 | ( )  MEGTRON 6 | ( )  NELCO-4000-13 | ( )  ROGERS 4350B | ( ) ROGERS 3003 | ( ) ARLON 85N | ( ) EM370D | ( )  OTHER ________________________ | UL FLAMMABILITY RATING 94V-0. BOARD MATERIAL & CONSTRUCTION SHALL MEET THE REQUIREMENTS OF UL796/UL796F. | BONDABLE GOLD OVER 100-150 MICRO INCHES OF NICKEL | NICKEL UNDER 30 MICRO-INCHES (.0003') OF GOLD | 0.100 INCH CLEARANCE FROM ALL COPPER FEATURES, | THE STARTING COPPER WEIGHT/THICKNESS CAN VARY AS LONG AS THE FINISHED COPPER | WEIGHT/THICKNESS IS NOT LESS THAN THE SPECIFIED VALUE. | UNLESS OTHERWISE SPECIFIED | HOMOGENOUS MATERIALS IN THIS BOARD SHALL BE COMPLAINT WITH THE EU DIRECTIVE 2002/95/EC | WORKMANSHIP SHALL CONFORM TO IPC-A-600, CLASS 2. | 21.  INTENTIONAL SHORTS: | 17.  FINAL ELECTRICAL TEST TO BE PERFORMED USING PROVIDED IPC-D-356A NETLIST OR ODB++ FORMAT FILE. | 22.  PEMNUTS: | 23.  MANUFACTURER TO ETCH/STAMP WITH PERMANENT NON-CONDUCTIVE INK | ON SECONDARY SIDE UNLESS OTHERWISE SPECIFIED: | 18.  A TIME DOMAIN REFLECTOMETER REPORT (TDR) FOR EACH IMPEDANCE CONTROLLED LAYER & A CERTIFICATE | 19.  IF PRESENT, ALL BLIND/BURIED VIAS WITH AN ASPECT RATIO <1:1 TO BE PLATED SHUT WITH COPPER WHEN | 20.  FOR VIA FILL INFORMATION REFER TO DRILL CHART: | 25. PANELIZATION: | 27.  MINIMUM DESIGN LINE WIDTH IS .010 INCH. | 28.  MINIMUM DESIGN LINE SPACING IS .006 INCH. | IS ACCEPTABLE, ALL OTHER INSTANCES MUST BE REPORTED. | IF AN INTENTIONAL SHORT REPORT IS SUPPLIED AND DOES NOT MATCH THE FAB DATA THEN | THE PCB SHALL HAVE A VERIFICATION STAMP. | (X)  NON-CONDUCTIVE EPOXY FILL ALL LESS THAN 0.012 INCHES DRILLED VIAS | ( )  COPPER FILL ALL 0.XXXX INCHES DRILLED VIAS | ( ) PEMNUTS TO BE INSTALLED BY FABRICATOR | ( ) PEMNUTS NOT TO BE INSTALLED BY FABRICATOR | (X) NOT APPLICABLE | USED AS VIA-IN-PAD OR AS A STACKED VIA. BLIND/BURIED VIAS WITH AN ASPECT RATIO >1:1 TO BE FILLED | A. UL CODE-FLAMMABILITY RATING FOR THOSE APPROVED MATERIALS(IF APPLICABLE) | B. DATE CODE | C. LOT NUMBER | D. MANUFACTURER LOGO | BOARDS TO BE SHIPPED IN ARRAY AND KEPT INTACT | PANEL TO BE SUBJECTED TO CUSTOMERS APPROVAL | PANEL SOLDER PASTE STENCIL GERBER TO BE PROVIDED TO ANALOG | CAN'T BE PERFORMED BECAUSE THE TRACE LENGTH IS TOO SHORT ON THE OUTER LAYERS AT THE PIN ESCAPES | ADI APPROVAL IS REQUIRED. | OF COMPLIANCE SHALL BE PROVIDED BY VENDOR AT TIME OF SHIPMENT. INSTANCES WHERE TDR TESTING | WITH NON-CONDUCTIVE EPOXY. | 2 | TOOLING: | FINISH: | NOTES: | MATERIAL: | TESTING: | MISCELLANEOUS:
User.18: 08-      -07 | L2-GND PLANE
User.19: 08-      -07 | L2-SIGNAL/GND
User.20: 08-      -08 | L3-SIGNAL/GND
User.21: L5-SIGNAL/GND | 08-      -10
User.45: 2 | FIGURE | FINISHED_SIZE | 6.0 | 10.0 | 45.0 | 100.0 | 185.0 | DRILL CHART: TOP to BOTTOM | ALL UNITS ARE IN MILS | TOLERANCE_DRILL | +3.0/-3.0 | +0.0/-0.0 | +2.0/-2.0 | PLATED | NON-PLATED | QTY | 18 | 389 | 6 | 15 | 4 | 432 | TOTAL HOLES:
